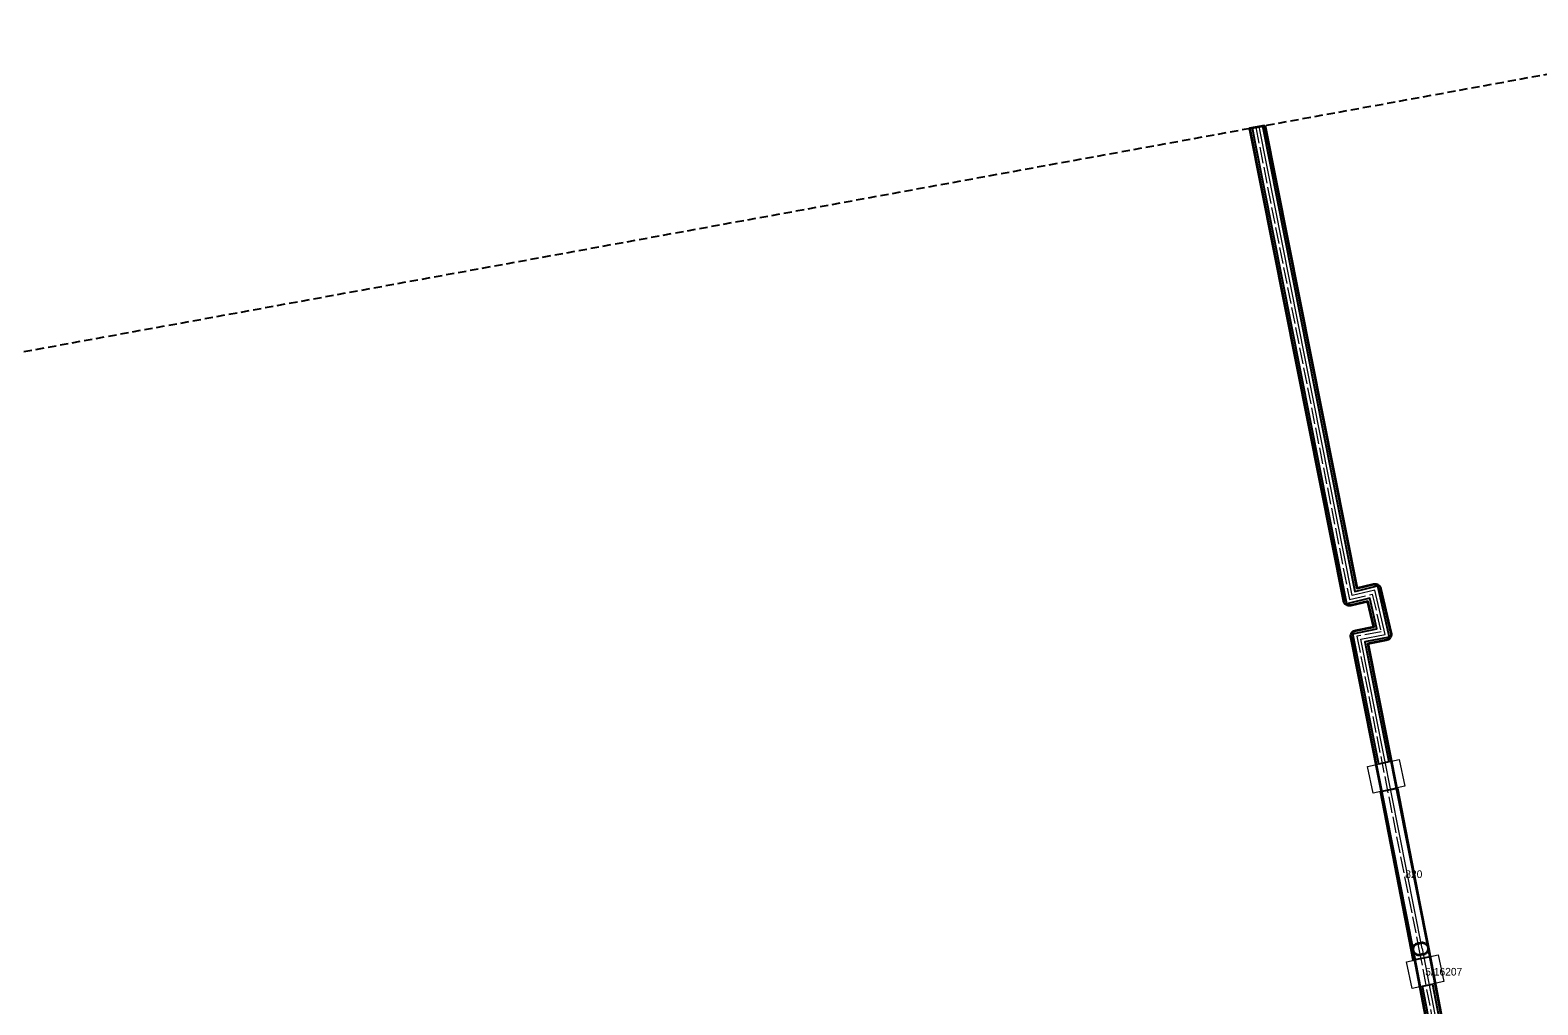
# Model space of a CAD drawing. Extents: x -452602 to -451136, y -1100088 to -1099653.
# Drawn here: x -452373.5 to -452196.4, y -1099954.9 to -1099840.4 of the extents above; entities that cross this region are included whole.
import ezdxf

# ---------------------------------------------------------------- set-up
doc = ezdxf.new("R2010")
doc.units = 0
doc.header["$LTSCALE"] = 0.32
doc.linetypes.add('LONG_DASHED', pattern=[7.5, 6, -1.5])
doc.linetypes.add('MEDIUM_DASHED', pattern=[4.5, 3, -1.5])
for name, color, linetype, lineweight in [('2', 7, 'Continuous', 13), ('3', 7, 'Continuous', 25), ('62', 7, 'MEDIUM_DASHED', 25), ('8', 7, 'Continuous', 35)]:
    doc.layers.add(name, color=color, linetype=linetype, lineweight=lineweight)

msp = doc.modelspace()

# ---------------------------------------------------------------- linework, layer by layer
at = {"layer": '2', "linetype": 'LONG_DASHED'}
for points in [[(-452229.569, -1099851.777), (-452218.546, -1099907.263), (-452215.876, -1099906.618), (-452214.853, -1099911.026), (-452217.69, -1099911.572), (-452210.396, -1099948.317)], [(-452210.396, -1099948.317), (-452200.553, -1099999.776), (-452231.662, -1100007.397), (-452230.555, -1100012.096), (-452230.695, -1100012.136)]]:
    msp.add_lwpolyline(points, dxfattribs=at)
at = {"layer": '2'}
for points in [[(-452210.005, -1099948.241), (-452217.221, -1099911.888), (-452214.369, -1099911.339), (-452215.579, -1099906.133), (-452218.234, -1099906.778), (-452229.182, -1099851.706)], [(-452210.005, -1099948.241), (-452200.09, -1100000.074), (-452231.262, -1100007.711), (-452230.221, -1100012.302), (-452230.625, -1100012.393)]]:
    msp.add_lwpolyline(points, dxfattribs=at)
at = {"layer": '3'}
for points in [[(-452215.123, -1099926.571), (-452218.16, -1099911.275), (-452215.336, -1099910.711), (-452216.175, -1099907.101), (-452218.86, -1099907.751), (-452229.668, -1099853.329), (-452229.962, -1099851.848), (-452228.789, -1099851.635), (-452226.243, -1099864.439), (-452217.924, -1099906.291), (-452215.28, -1099905.65), (-452213.885, -1099911.654), (-452216.75, -1099912.204), (-452213.948, -1099926.318)], [(-452214.918, -1099929.802), (-452212.938, -1099929.397), (-452209.092, -1099949.232), (-452211.076, -1099949.616)], [(-452231.044, -1100006.833), (-452201.018, -1099999.478), (-452206.361, -1099971.542), (-452209.976, -1099952.669), (-452208.8, -1099952.407), (-452205.439, -1099969.98), (-452199.625, -1100000.373), (-452230.785, -1100008.006)]]:
    msp.add_lwpolyline(points, close=True, dxfattribs=at)
at = {"layer": '3', "lineweight": 13}
for points in [[(-452215.769, -1099929.985), (-452216.451, -1099926.861), (-452212.738, -1099926.051), (-452212.057, -1099929.176)], [(-452211.178, -1099952.931), (-452211.859, -1099949.807), (-452208.147, -1099948.997), (-452207.465, -1099952.122)]]:
    msp.add_lwpolyline(points, close=True, dxfattribs=at)
at = {"layer": '62'}
msp.add_lwpolyline([(-451137.485, -1099816.961), (-452572.169, -1100088.267), (-452602.314, -1099919.678), (-451137.485, -1099652.838), (-451136.368, -1099701.963)], close=True, dxfattribs=at)
at = {"layer": '8'}
msp.add_lwpolyline([(-452228.494, -1099851.581), (-452217.69, -1099905.925), (-452215.743, -1099905.453), (-452215.634, -1099905.436), (-452215.524, -1099905.436), (-452215.415, -1099905.453), (-452215.31, -1099905.487), (-452215.211, -1099905.538), (-452215.122, -1099905.603), (-452215.044, -1099905.681), (-452214.98, -1099905.771), (-452214.93, -1099905.87), (-452214.897, -1099905.975), (-452213.687, -1099911.181), (-452213.67, -1099911.292), (-452213.672, -1099911.405), (-452213.691, -1099911.516), (-452213.728, -1099911.622), (-452213.782, -1099911.721), (-452213.85, -1099911.81), (-452213.932, -1099911.887), (-452214.026, -1099911.95), (-452214.128, -1099911.997), (-452214.236, -1099912.027), (-452216.397, -1099912.442), (-452209.318, -1099948.104), (-452209.304, -1099948.223), (-452209.311, -1099948.342), (-452209.338, -1099948.458), (-452209.384, -1099948.568), (-452209.449, -1099948.668), (-452209.529, -1099948.756), (-452209.623, -1099948.829), (-452209.728, -1099948.885), (-452209.841, -1099948.923), (-452209.959, -1099948.941), (-452210.078, -1099948.938), (-452210.187, -1099948.983), (-452210.301, -1099949.008), (-452210.418, -1099949.015), (-452210.535, -1099949.001), (-452210.647, -1099948.969), (-452210.753, -1099948.918), (-452210.849, -1099948.85), (-452210.931, -1099948.767), (-452210.999, -1099948.671), (-452211.05, -1099948.565), (-452211.083, -1099948.453), (-452218.377, -1099911.708), (-452218.39, -1099911.598), (-452218.385, -1099911.488), (-452218.364, -1099911.38), (-452218.325, -1099911.277), (-452218.271, -1099911.181), (-452218.203, -1099911.094), (-452218.121, -1099911.02), (-452218.029, -1099910.959), (-452217.929, -1099910.913), (-452217.823, -1099910.884), (-452215.699, -1099910.475), (-452216.398, -1099907.464), (-452218.382, -1099907.944), (-452218.493, -1099907.962), (-452218.606, -1099907.961), (-452218.717, -1099907.942), (-452218.824, -1099907.906), (-452218.924, -1099907.853), (-452219.013, -1099907.785), (-452219.091, -1099907.704), (-452219.155, -1099907.61), (-452219.202, -1099907.508), (-452219.233, -1099907.4), (-452230.258, -1099851.902)], close=True, dxfattribs=at)
msp.add_lwpolyline([(-452201.366, -1099999.255), (-452211.084, -1099948.448), (-452211.095, -1099948.331), (-452211.086, -1099948.214), (-452211.059, -1099948.1), (-452211.012, -1099947.992), (-452210.948, -1099947.894), (-452210.868, -1099947.808), (-452210.775, -1099947.736), (-452210.672, -1099947.681), (-452210.56, -1099947.643), (-452210.444, -1099947.625), (-452210.327, -1099947.627), (-452210.218, -1099947.581), (-452210.104, -1099947.555), (-452209.986, -1099947.548), (-452209.869, -1099947.561), (-452209.756, -1099947.593), (-452209.649, -1099947.643), (-452209.553, -1099947.711), (-452209.47, -1099947.794), (-452209.401, -1099947.89), (-452209.35, -1099947.996), (-452209.317, -1099948.109), (-452199.402, -1099999.943)], dxfattribs=at)

# ---------------------------------------------------------------- texts
at = {"layer": '3'}
for s, p in [('820 ', (-452212.006, -1099939.961)), ('5/16207', (-452209.662, -1099951.413))]:
    msp.add_text(s, height=0.9, dxfattribs=at).set_placement(p)

doc.saveas('drawing.dxf')
